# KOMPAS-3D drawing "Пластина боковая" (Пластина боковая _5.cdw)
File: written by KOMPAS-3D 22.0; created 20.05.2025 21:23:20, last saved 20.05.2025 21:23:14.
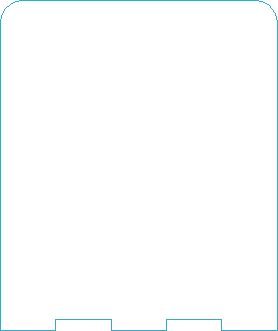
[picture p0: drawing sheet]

Sheet 1: A4, portrait

Document properties: Автор: TC; Масса: 0.779593; Полное имя файла: Пластина боковая.m3d

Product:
- Part/product: Пластина боковая
    Масса: 0.779593
    Форматы листов документа: A4

Title block, sheet 1: Наименование: Пластина боковая; Материал: Сталь 10 ГОСТ 1050-2013; Масса: 0,27; Количество листов документа: 1; Форматы листов документа: A4

Views: Вид 1, Спереди
Referenced files in D:\Работа\2025\5. Май\Задание №6 - Тележка для крыши\3Д\Узел монтажный\: Пластина боковая.m3d
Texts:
  Без оформления
Dimensions and other numbers on the sheet: 1:1; 1; 0,27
